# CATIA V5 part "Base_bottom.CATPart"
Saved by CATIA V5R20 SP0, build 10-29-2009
Part number: Base_bottom
Source: Unknown
Bounding box of the stored display mesh (mm): x 0 to 450, y 0 to 450, z -54.55 to -42.55
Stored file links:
  C:\Users\Ikarus\OneDrive - FH JOANNEUM\BAC - Arbeit 1\CAD Modell\CAD-Modell-Step files\Base\Base_bottom.CATPart
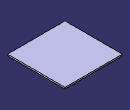
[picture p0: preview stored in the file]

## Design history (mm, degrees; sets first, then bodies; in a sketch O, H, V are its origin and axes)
Body1 (main body)
  Solid1 "Hauptkörper": solid without history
